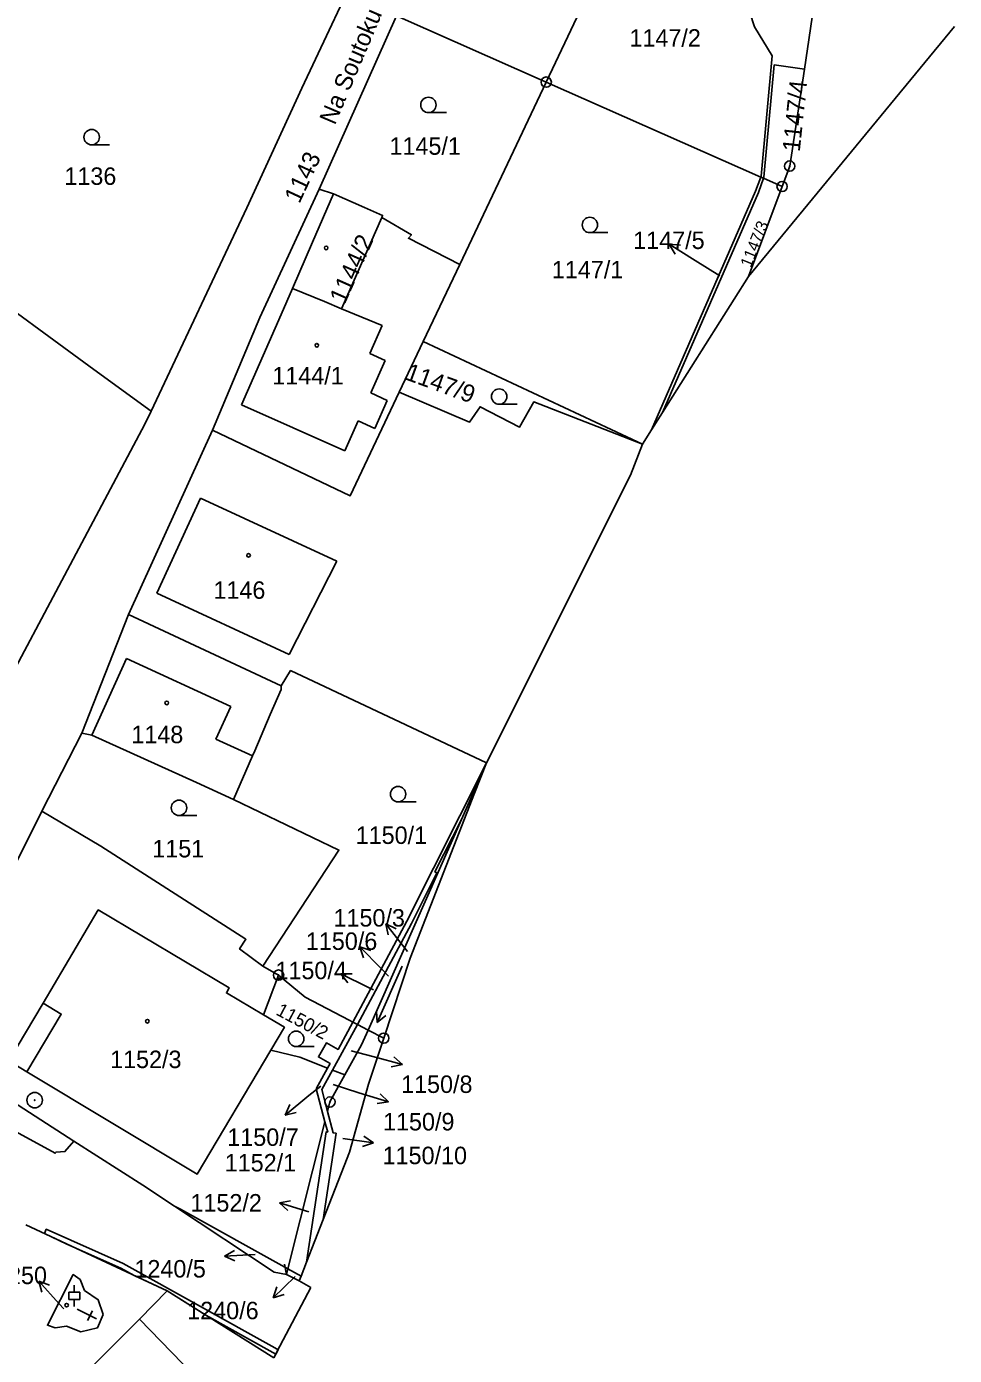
# Model space of a CAD drawing. Extents: x -562167 to -556918, y -1077891 to -1070763.
# Drawn here: x -559220.3 to -559130, y -1075093.3 to -1074964 of the extents above; entities that cross this region are included whole.
import ezdxf

# ---------------------------------------------------------------- set-up
doc = ezdxf.new("R2010")
doc.units = 0
for name, color, linetype in [('Hranice parcel', 7, 'Continuous'), ('Parcelní čísla', 7, 'Continuous'), ('Pop  PČ popisy', 7, 'Continuous'), ('Vnitřní kresba', 7, 'Continuous'), ('Věcná břemena k části', 7, 'Continuous'), ('Značky bodu BP', 7, 'Continuous'), ('Značky budov', 7, 'Continuous'), ('Značky kultur', 7, 'Continuous')]:
    doc.layers.add(name, color=color, linetype=linetype)

msp = doc.modelspace()

# ---------------------------------------------------------------- linework, layer by layer
at = {"layer": 'Hranice parcel'}
for p, q in [((-559143.24, -1074958.98), (-559144.63, -1074968.18)), ((-559191.88, -1074979.85), (-559184.32, -1074962.99)), ((-559169.76, -1074969.43), (-559184.32, -1074962.99)), ((-559130.02, -1074964.02), (-559150.06, -1074988.36)), ((-559178.18, -1074987.19), (-559169.76, -1074969.43)), ((-559148.87, -1074978.67), (-559169.76, -1074969.43)), ((-559148.87, -1074978.67), (-559148.6, -1074978.79)), ((-559148.6, -1074978.79), (-559146.8, -1074979.59)), ((-559190.46, -1074980.29), (-559191.88, -1074979.85)), ((-559146.8, -1074979.59), (-559150.06, -1074988.36)), ((-559181.73, -1074994.67), (-559178.18, -1074987.19)), ((-559150.06, -1074988.36), (-559158.44, -1075001.58)), ((-559184.07, -1074999.61), (-559181.73, -1074994.67)), ((-559181.73, -1074994.67), (-559160.4, -1075004.67)), ((-559158.44, -1075001.58), (-559159.51, -1075003.26)), ((-559210.42, -1075021.25), (-559202.24, -1075003.31)), ((-559159.51, -1075003.26), (-559160.4, -1075004.67)), ((-559161.54, -1075007.68), (-559160.4, -1075004.67)), ((-559175.59, -1075035.66), (-559161.54, -1075007.68)), ((-559214.97, -1075032.79), (-559210.42, -1075021.25)), ((-559210.42, -1075021.25), (-559195.58, -1075028.18)), ((-559218.86, -1075040.37), (-559214.97, -1075032.79)), ((-559175.59, -1075035.66), (-559178.02, -1075041.17)), ((-559222.24, -1075047.15), (-559218.86, -1075040.37)), ((-559178.02, -1075041.17), (-559187.09, -1075061.68)), ((-559197.35, -1075055.46), (-559195.82, -1075056.32)), ((-559195.82, -1075056.32), (-559197.29, -1075060.19)), ((-559190.57, -1075065.57), (-559188.14, -1075061.13)), ((-559188.14, -1075061.13), (-559188.6, -1075060.89)), ((-559188.14, -1075061.13), (-559187.09, -1075061.68)), ((-559187.09, -1075061.68), (-559185.58, -1075062.46)), ((-559189.35, -1075066.04), (-559190.57, -1075065.57)), ((-559194.92, -1075084.9), (-559191.3, -1075070.59)), ((-559206.67, -1075087.05), (-559220.42, -1075080.63)), ((-559191.47, -1075080.09), (-559193.1, -1075084.26)), ((-559195.06, -1075085.44), (-559194.92, -1075084.9)), ((-559194.92, -1075084.9), (-559193.63, -1075085.62)), ((-559193.1, -1075084.26), (-559193.63, -1075085.62)), ((-559193.81, -1075086.07), (-559195.06, -1075085.44)), ((-559193.63, -1075085.62), (-559193.81, -1075086.07)), ((-559192.66, -1075086.73), (-559193.81, -1075086.07)), ((-559196.28, -1075093.58), (-559206.67, -1075087.05)), ((-559195.97, -1075092.98), (-559192.66, -1075086.73))]:
    msp.add_line(p, q, dxfattribs=at)
for points in [[(-559169.76, -1074969.43), (-559166.46, -1074962.46), (-559156.61, -1074942.12)], [(-559148.87, -1074978.67), (-559148.84, -1074978.59), (-559147.78, -1074966.86), (-559149.5, -1074964.05), (-559156.61, -1074942.12)], [(-559208.23, -1075001.46), (-559198.9, -1074981.65), (-559193.56, -1074970.02), (-559187.15, -1074956.44)], [(-559144.63, -1074968.18), (-559147.56, -1074967.76), (-559148.56, -1074978.69), (-559148.6, -1074978.79)], [(-559144.63, -1074968.18), (-559146.06, -1074977.6), (-559146.8, -1074979.59)], [(-559159.51, -1075003.26), (-559149.4, -1074980.04), (-559148.87, -1074978.67)], [(-559148.6, -1074978.79), (-559149.11, -1074980.17), (-559158.44, -1075001.58)], [(-559202.24, -1075003.31), (-559197.64, -1074992.32), (-559191.88, -1074979.85)], [(-559185.78, -1074982.6), (-559189.68, -1074991.48), (-559191.36, -1074990.78), (-559194.45, -1074989.5), (-559192.5, -1074984.99), (-559190.46, -1074980.29)], [(-559185.78, -1074982.6), (-559185.69, -1074982.4), (-559187.46, -1074981.63), (-559190.46, -1074980.29)], [(-559178.18, -1074987.19), (-559183.18, -1074984.62), (-559182.88, -1074984.28), (-559185.78, -1074982.6)], [(-559226.12, -1074988.37), (-559213.81, -1074997.38), (-559208.23, -1075001.46)], [(-559202.24, -1075003.31), (-559188.84, -1075009.68), (-559184.07, -1074999.61)], [(-559160.4, -1075004.67), (-559170.98, -1075000.55), (-559172.37, -1075003.01), (-559176.2, -1075001.02), (-559177.24, -1075002.52), (-559184.07, -1074999.61)], [(-559230.63, -1075043.7), (-559208.82, -1075002.71), (-559208.23, -1075001.46)], [(-559195.58, -1075028.18), (-559194.64, -1075026.7), (-559175.59, -1075035.66)], [(-559200.19, -1075039.23), (-559198.35, -1075034.98), (-559198.14, -1075034.49), (-559196.63, -1075030.97), (-559195.57, -1075028.53), (-559195.58, -1075028.18)], [(-559214.97, -1075032.79), (-559213.99, -1075032.99), (-559203.8, -1075037.57), (-559200.19, -1075039.23)], [(-559188.6, -1075060.89), (-559183.34, -1075051.07), (-559175.59, -1075035.66)], [(-559175.59, -1075035.66), (-559176.74, -1075038.62), (-559183.01, -1075054.67), (-559185.58, -1075062.46)], [(-559200.19, -1075039.23), (-559189.94, -1075044.16), (-559197.35, -1075055.46)], [(-559218.86, -1075040.37), (-559213.12, -1075043.79), (-559199, -1075052.84), (-559199.62, -1075053.78), (-559197.35, -1075055.46)], [(-559178.02, -1075041.17), (-559180.59, -1075046.28), (-559180.4, -1075046.38), (-559182.89, -1075051.29), (-559188.14, -1075061.13)], [(-559196.58, -1075063.63), (-559203.73, -1075075.69), (-559220.31, -1075065.75), (-559222.06, -1075064.67), (-559218.74, -1075059.06), (-559213.37, -1075049.98), (-559200.62, -1075057.57), (-559200.89, -1075058.05), (-559197.29, -1075060.19)], [(-559195.82, -1075056.32), (-559193.22, -1075058.47), (-559188.93, -1075060.72), (-559188.6, -1075060.89)], [(-559215.74, -1075072.47), (-559216.62, -1075073.49), (-559217.48, -1075073.54), (-559217.55, -1075073.66), (-559226.8, -1075068.62), (-559242.63, -1075059.8)], [(-559227.65, -1075059.72), (-559223.32, -1075067.62), (-559215.74, -1075072.47)], [(-559197.29, -1075060.19), (-559195.25, -1075061.4), (-559196.58, -1075063.63)], [(-559191.04, -1075065.38), (-559190.8, -1075064.94), (-559191.93, -1075064.28), (-559191.16, -1075062.92), (-559190.03, -1075063.55), (-559188.6, -1075060.89)], [(-559189.35, -1075066.04), (-559187.73, -1075063.12), (-559187.09, -1075061.68)], [(-559185.58, -1075062.46), (-559187.05, -1075066.94), (-559188.91, -1075073.54), (-559189.43, -1075074.87), (-559191.47, -1075080.09)], [(-559196.58, -1075063.63), (-559193.76, -1075064.32), (-559191.04, -1075065.38)], [(-559191.3, -1075070.59), (-559192.15, -1075067.38), (-559191.04, -1075065.38)], [(-559190.57, -1075065.57), (-559191.6, -1075067.46), (-559191.04, -1075069.59)], [(-559191.04, -1075069.59), (-559190.81, -1075068.67), (-559189.35, -1075066.04)], [(-559191.47, -1075080.09), (-559190.21, -1075071.71), (-559190.5, -1075071.68), (-559191.04, -1075069.59)], [(-559193.1, -1075084.26), (-559191.19, -1075071.58), (-559191.03, -1075071.6), (-559191.3, -1075070.59)], [(-559215.74, -1075072.47), (-559209.03, -1075076.77), (-559205.96, -1075078.8)], [(-559195.06, -1075085.44), (-559196.24, -1075085.22), (-559205.96, -1075078.8)], [(-559205.96, -1075078.8), (-559205.36, -1075079.11), (-559194.92, -1075084.9)], [(-559212.89, -1075089.34), (-559213.39, -1075087.92), (-559214.7, -1075087), (-559215.13, -1075085.95), (-559215.8, -1075085.46), (-559218.32, -1075090.39), (-559217.57, -1075090.66), (-559216.45, -1075090.48), (-559215.08, -1075091.05), (-559213.44, -1075090.63), (-559212.89, -1075089.34)], [(-559227.09, -1075110.95), (-559219.1, -1075099.57), (-559209.37, -1075089.79), (-559206.67, -1075087.05)], [(-559195.97, -1075092.98), (-559196.08, -1075093.2), (-559196.28, -1075093.58)]]:
    msp.add_lwpolyline(points, dxfattribs=at)
at = {"layer": 'Pop  PČ popisy'}
for p, q in [((-559155.25, -1074986.79), (-559157.8, -1074985.2)), ((-559157.8, -1074985.2), (-559156.68, -1074985.31)), ((-559157.8, -1074985.2), (-559157.21, -1074986.16)), ((-559152.85, -1074988.28), (-559155.25, -1074986.79)), ((-559183.52, -1075053.69), (-559185.37, -1075051.32)), ((-559185.37, -1075051.32), (-559184.36, -1075051.81)), ((-559185.37, -1075051.32), (-559185.15, -1075052.42)), ((-559185.8, -1075055.72), (-559187.89, -1075053.56)), ((-559187.89, -1075053.56), (-559186.83, -1075053.93)), ((-559187.89, -1075053.56), (-559187.55, -1075054.63)), ((-559183.26, -1075054.03), (-559183.52, -1075053.69)), ((-559189.77, -1075056.2), (-559188.65, -1075056.19)), ((-559187.07, -1075057.52), (-559189.77, -1075056.2)), ((-559189.77, -1075056.2), (-559189.09, -1075057.09)), ((-559185.12, -1075056.43), (-559185.8, -1075055.72)), ((-559186.57, -1075057.76), (-559187.07, -1075057.52)), ((-559188.75, -1075063.68), (-559186.65, -1075064.25)), ((-559186.65, -1075064.25), (-559183.75, -1075065.03)), ((-559183.75, -1075065.03), (-559184.59, -1075064.28)), ((-559183.75, -1075065.03), (-559184.85, -1075065.25)), ((-559191.7, -1075067.13), (-559192.86, -1075068.05)), ((-559190.51, -1075066.98), (-559187.99, -1075067.77)), ((-559192.86, -1075068.05), (-559195.19, -1075069.94)), ((-559187.99, -1075067.77), (-559185.12, -1075068.65)), ((-559185.12, -1075068.65), (-559185.93, -1075067.88)), ((-559195.19, -1075069.94), (-559194.73, -1075068.92)), ((-559195.19, -1075069.94), (-559194.1, -1075069.7)), ((-559185.12, -1075068.65), (-559186.22, -1075068.83)), ((-559189.55, -1075072.23), (-559186.58, -1075072.65)), ((-559186.58, -1075072.65), (-559187.5, -1075072.01)), ((-559186.58, -1075072.65), (-559187.64, -1075073)), ((-559195.74, -1075078.47), (-559194.64, -1075078.29)), ((-559192.87, -1075079.35), (-559195.74, -1075078.47)), ((-559195.74, -1075078.47), (-559194.93, -1075079.24)), ((-559201.09, -1075083.68), (-559200.11, -1075083.12)), ((-559198.09, -1075083.52), (-559201.09, -1075083.68)), ((-559201.09, -1075083.68), (-559200.06, -1075084.12)), ((-559217.16, -1075088.32), (-559219.17, -1075086.09)), ((-559219.17, -1075086.09), (-559218.13, -1075086.5)), ((-559219.17, -1075086.09), (-559218.87, -1075087.17)), ((-559194.19, -1075085.64), (-559196.35, -1075087.73)), ((-559196.35, -1075087.73), (-559195.98, -1075086.67)), ((-559196.35, -1075087.73), (-559195.28, -1075087.39)), ((-559216.72, -1075088.8), (-559217.16, -1075088.32))]:
    msp.add_line(p, q, dxfattribs=at)
at = {"layer": 'Vnitřní kresba'}
for p, q in [((-559195.55, -1074992.04), (-559194.45, -1074989.5)), ((-559199.43, -1075000.84), (-559195.55, -1074992.04)), ((-559189.68, -1074991.48), (-559185.73, -1074993.11)), ((-559186.94, -1074995.85), (-559185.73, -1074993.11)), ((-559186.94, -1074995.85), (-559185.44, -1074996.52)), ((-559186.85, -1074999.68), (-559185.44, -1074996.52)), ((-559186.85, -1074999.68), (-559185.23, -1075000.4)), ((-559199.43, -1075000.84), (-559189.36, -1075005.32)), ((-559186.45, -1075003.12), (-559185.23, -1075000.4)), ((-559189.36, -1075005.32), (-559188.06, -1075002.4)), ((-559188.06, -1075002.4), (-559186.45, -1075003.12)), ((-559207.66, -1075019.16), (-559203.43, -1075009.9)), ((-559203.43, -1075009.9), (-559190.16, -1075016.04)), ((-559194.79, -1075025.13), (-559190.16, -1075016.04)), ((-559207.66, -1075019.16), (-559194.79, -1075025.13)), ((-559213.99, -1075032.99), (-559210.61, -1075025.51)), ((-559210.61, -1075025.51), (-559200.48, -1075030.18)), ((-559201.91, -1075033.37), (-559200.48, -1075030.18)), ((-559201.91, -1075033.37), (-559198.35, -1075034.98)), ((-559195.23, -1075084.46), (-559195.06, -1075085.44)), ((-559209.37, -1075089.79), (-559201.11, -1075098.26))]:
    msp.add_line(p, q, dxfattribs=at)
msp.add_lwpolyline([(-559218.74, -1075059.06), (-559216.98, -1075060.11), (-559220.31, -1075065.75)], dxfattribs=at)
at = {"layer": 'Věcná břemena k části'}
msp.add_lwpolyline([(-559218.62, -1075081.47), (-559216.43, -1075082.49), (-559211.17, -1075084.83), (-559209.87, -1075085.56), (-559206.67, -1075087.05), (-559202.9, -1075089.42), (-559196.38, -1075093.04), (-559196.08, -1075093.2), (-559195.85, -1075092.77), (-559196.17, -1075092.58), (-559210.95, -1075084.39), (-559218.44, -1075081.05)], close=True, dxfattribs=at)
at = {"layer": 'Značky bodu BP'}
for centre, radius in [((-559169.76, -1074969.43), 0.5), ((-559169.76, -1074969.43), 0.0303), ((-559146.06, -1074977.6), 0.5), ((-559146.06, -1074977.6), 0.0303), ((-559146.8, -1074979.59), 0.5), ((-559146.8, -1074979.59), 0.0303), ((-559195.82, -1075056.32), 0.5), ((-559195.82, -1075056.32), 0.0303), ((-559185.58, -1075062.46), 0.5), ((-559185.58, -1075062.46), 0.0303), ((-559219.56, -1075068.49), 0.75), ((-559190.81, -1075068.67), 0.5), ((-559219.56, -1075068.49), 0.03), ((-559190.81, -1075068.67), 0.0303)]:
    msp.add_circle(centre, radius, dxfattribs=at)
at = {"layer": 'Značky budov'}
for p, q in [((-559213.55, -1075089.77), (-559215.42, -1075088.82)), ((-559213.94, -1075088.99), (-559214.41, -1075089.92))]:
    msp.add_line(p, q, dxfattribs=at)
for centre in [(-559191.18, -1074985.56), (-559192.09, -1074995.04), (-559198.74, -1075015.48), (-559206.7, -1075029.84), (-559208.59, -1075060.81), (-559216.45, -1075088.44)]:
    msp.add_circle(centre, 0.175, dxfattribs=at)
at = {"layer": 'Značky kultur'}
for p, q in [((-559181.23, -1074972.4), (-559179.48, -1074972.4)), ((-559214.01, -1074975.54), (-559212.26, -1074975.54)), ((-559165.51, -1074984.08), (-559163.76, -1074984.08)), ((-559174.34, -1075000.78), (-559172.59, -1075000.78)), ((-559184.18, -1075039.47), (-559182.43, -1075039.47)), ((-559205.51, -1075040.8), (-559203.76, -1075040.8)), ((-559183.78, -1075055.45), (-559186.21, -1075060.93)), ((-559186.21, -1075060.93), (-559186.28, -1075059.84)), ((-559186.21, -1075060.93), (-559185.36, -1075060.24)), ((-559194.1, -1075063.27), (-559192.35, -1075063.27)), ((-559215.71, -1075087.18), (-559215.71, -1075086.48)), ((-559216.24, -1075087.18), (-559215.18, -1075087.18)), ((-559216.24, -1075087.88), (-559216.24, -1075087.18)), ((-559215.18, -1075087.88), (-559215.18, -1075087.18)), ((-559216.24, -1075087.88), (-559215.18, -1075087.88)), ((-559215.71, -1075088.58), (-559215.71, -1075087.88))]:
    msp.add_line(p, q, dxfattribs=at)
for centre in [(-559181.23, -1074971.65), (-559214.01, -1074974.79), (-559165.51, -1074983.33), (-559174.34, -1075000.03), (-559184.18, -1075038.72), (-559205.51, -1075040.05), (-559194.1, -1075062.52)]:
    msp.add_circle(centre, 0.75, dxfattribs=at)

# ---------------------------------------------------------------- texts
at = {"layer": 'Parcelní čísla'}
for s, p in [('1147/2', (-559161.66, -1074965.98)), ('1145/1', (-559185.02, -1074976.5)), ('1136', (-559216.67, -1074979.43)), ('1147/5', (-559161.29, -1074985.67)), ('1147/1', (-559169.21, -1074988.53)), ('1144/1', (-559196.43, -1074998.85)), ('1146', (-559202.16, -1075019.71)), ('1148', (-559210.15, -1075033.76)), ('1150/1', (-559188.31, -1075043.56)), ('1151', (-559208.11, -1075044.87)), ('1150/3', (-559190.47, -1075051.6)), ('1150/6', (-559193.16, -1075053.87)), ('1150/4', (-559196.12, -1075056.72)), ('1152/3', (-559212.22, -1075065.37)), ('1150/8', (-559183.89, -1075067.79)), ('1150/9', (-559185.65, -1075071.44)), ('1150/7', (-559200.81, -1075072.94)), ('1150/10', (-559185.69, -1075074.72)), ('1152/1', (-559201.06, -1075075.43)), ('1152/2', (-559204.4, -1075079.33)), ('1240/5', (-559209.85, -1075085.75)), ('1250', (-559223.42, -1075086.39)), ('1240/6', (-559204.71, -1075089.81))]:
    msp.add_text(s, height=1.7, dxfattribs=at).set_placement(p)
for s, height, rotation, p in [('1147/4', 1.7, 84, (-559145.08, -1074976.26)), ('1143', 1.7, 65, (-559193.79, -1074981.32)), ('1147/3', 1.139, 68, (-559149.85, -1074987.55)), ('1144/2', 1.7, 66, (-559189.37, -1074991.11)), ('1147/9', 1.7, 340, (-559183.6, -1074998.33)), ('1150/2', 1.309, 332, (-559196.16, -1075060.13))]:
    msp.add_text(s, height=height, rotation=rotation, dxfattribs=at).set_placement(p)
at = {"layer": 'Pop  PČ popisy'}
msp.add_text('Na Soutoku', height=1.7, rotation=67, dxfattribs=at).set_placement((-559190.34, -1074973.68))

doc.saveas('drawing.dxf')
